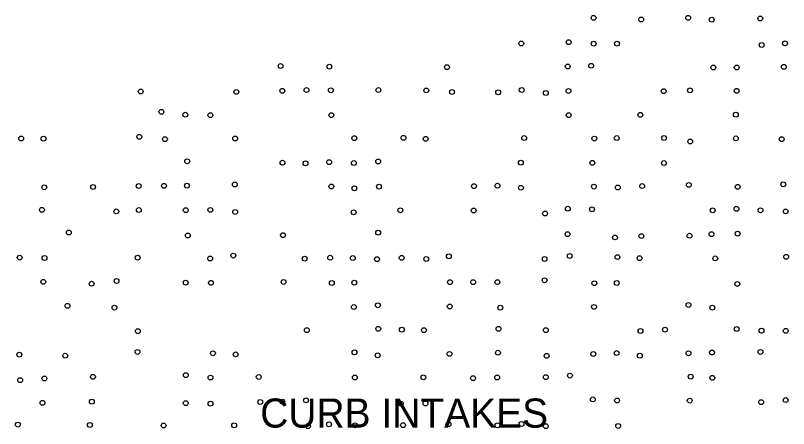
# Model space of a CAD drawing. Extents: x 20503438 to 20508873, y 7964251 to 7984667.
# Drawn here: x 20505042.3 to 20505360.8, y 7970624.5 to 7970794.8 of the extents above; entities that cross this region are included whole.
import ezdxf

# ---------------------------------------------------------------- set-up
doc = ezdxf.new("R2010")
doc.units = 0
doc.layers.add('SurSurveyPoints', color=7, linetype='Continuous')
doc.layers.add('SurTxtDrainage', color=7, linetype='Continuous')

msp = doc.modelspace()

# ---------------------------------------------------------------- linework, layer by layer
at = {"layer": 'SurSurveyPoints'}
for centre in [(20505280.47, 7970793.84), (20505300.05, 7970793.14), (20505319.42, 7970793.83), (20505329.14, 7970793.08), (20505349.12, 7970793.59), (20505250.68, 7970783.25), (20505270.21, 7970783.81), (20505280.51, 7970783.22), (20505290.11, 7970783.21), (20505349.71, 7970782.67), (20505359.33, 7970783.34), (20505151.54, 7970773.97), (20505171.66, 7970773.73), (20505220.06, 7970773.51), (20505269.82, 7970773.78), (20505279.49, 7970774.09), (20505329.8, 7970773.35), (20505339.43, 7970773.39), (20505358.81, 7970773.66), (20505093.94, 7970763.45), (20505133.3, 7970763.31), (20505152.26, 7970763.73), (20505162.21, 7970764.07), (20505172.27, 7970763.99), (20505191.83, 7970764.07), (20505211.54, 7970763.92), (20505222.14, 7970763.29), (20505250.88, 7970764.08), (20505270.13, 7970763.71), (20505309.33, 7970763.59), (20505320.2, 7970763.95), (20505339.39, 7970763.74), (20505241.17, 7970763.14), (20505260.81, 7970762.87), (20505102.46, 7970755.08), (20505112.33, 7970753.9), (20505122.64, 7970753.74), (20505172.47, 7970753.7), (20505270.21, 7970753.72), (20505299.71, 7970753.85), (20505339.07, 7970753.93), (20505093.36, 7970744.76), (20505181.94, 7970744.22), (20505202.2, 7970744.39), (20505251.87, 7970744.28), (20505290, 7970744.28), (20505309.51, 7970744.29), (20505339.09, 7970744.13), (20505044.71, 7970744.09), (20505053.91, 7970744.01), (20505103.9, 7970743.81), (20505132.86, 7970744.09), (20505211.3, 7970743.97), (20505280.77, 7970744.05), (20505320.28, 7970742.87), (20505357.93, 7970743.81), (20505113.04, 7970734.71), (20505191.75, 7970734.59), (20505152.33, 7970734.11), (20505161.78, 7970733.86), (20505171.56, 7970734.32), (20505181.71, 7970733.97), (20505250.51, 7970734.12), (20505279.94, 7970734.08), (20505309.44, 7970733.97), (20505132.68, 7970725.1), (20505358.6, 7970725.21), (20505054.2, 7970723.98), (20505074.31, 7970724.11), (20505093.08, 7970724.5), (20505103.51, 7970724.55), (20505112.96, 7970724.65), (20505172.47, 7970724.32), (20505181.96, 7970723.55), (20505192.11, 7970724.22), (20505231.2, 7970724.46), (20505240.89, 7970724.61), (20505250.54, 7970723.78), (20505280.6, 7970724.27), (20505290.44, 7970723.87), (20505300.47, 7970724.48), (20505319.69, 7970724.96), (20505339.82, 7970724.18), (20505053.24, 7970714.7), (20505083.88, 7970714.03), (20505093.17, 7970714.59), (20505112.48, 7970714.54), (20505122.62, 7970714.65), (20505132.86, 7970713.81), (20505181.64, 7970713.63), (20505200.88, 7970714.51), (20505231.06, 7970714.41), (20505260.49, 7970713.17), (20505269.85, 7970715.14), (20505279.82, 7970714.89), (20505329.52, 7970714.48), (20505339.35, 7970715.1), (20505349.23, 7970714.51), (20505359.57, 7970714.04), (20505064.35, 7970705.31), (20505113.35, 7970704.11), (20505152.52, 7970704.23), (20505191.73, 7970705.27), (20505269.77, 7970704.66), (20505289.29, 7970703.3), (20505300.16, 7970703.85), (20505320, 7970704), (20505329.01, 7970704.65), (20505339.78, 7970704.84), (20505044.09, 7970694.99), (20505054.3, 7970694.83), (20505092.69, 7970694.94), (20505122.56, 7970694.63), (20505132.07, 7970695.81), (20505161.48, 7970694.55), (20505171.96, 7970694.93), (20505181.29, 7970694.79), (20505191.25, 7970694.36), (20505201.44, 7970694.87), (20505211.54, 7970694.39), (20505220.86, 7970695.52), (20505260.29, 7970694.42), (20505270.61, 7970695.65), (20505290.29, 7970695.19), (20505299.42, 7970694.77), (20505330.59, 7970694.65), (20505359.77, 7970695.3), (20505053.8, 7970685), (20505073.72, 7970684.21), (20505083.99, 7970685.32), (20505112.43, 7970684.63), (20505122.89, 7970684.58), (20505152.79, 7970684.94), (20505172.63, 7970684.51), (20505181.9, 7970684.65), (20505221.31, 7970684.85), (20505230.88, 7970684.87), (20505240.86, 7970684.88), (20505260.29, 7970685.64), (20505280.76, 7970684.41), (20505290, 7970684.49), (20505339.68, 7970684.13), (20505063.76, 7970675.09), (20505083.14, 7970674.37), (20505181.7, 7970674.58), (20505191.58, 7970675.32), (20505221.22, 7970674.81), (20505242.02, 7970674.35), (20505280.64, 7970674.64), (20505319.59, 7970675.46), (20505329.39, 7970674.32), (20505092.74, 7970664.67), (20505162.33, 7970665.04), (20505191.77, 7970665.6), (20505201.5, 7970665.28), (20505210.58, 7970665.03), (20505241.28, 7970665.59), (20505260.8, 7970665.08), (20505299.8, 7970664.73), (20505309.87, 7970665.28), (20505339.42, 7970665.52), (20505349.64, 7970664.87), (20505359.62, 7970664.77), (20505043.93, 7970654.97), (20505092.58, 7970656.09), (20505123.68, 7970655.54), (20505133.06, 7970655.07), (20505181.99, 7970655.92), (20505221.1, 7970655.27), (20505241.06, 7970655.75), (20505280.38, 7970655.21), (20505289.96, 7970655.62), (20505319.59, 7970655.53), (20505329.26, 7970655.83), (20505349.2, 7970656.09), (20505062.85, 7970654.52), (20505191.55, 7970654.66), (20505261.16, 7970654.48), (20505299.49, 7970654.55), (20505074.24, 7970645.8), (20505112.49, 7970646.48), (20505122.7, 7970645.51), (20505142.54, 7970645.77), (20505182.14, 7970645.56), (20505210.32, 7970645.59), (20505240.73, 7970645.54), (20505260.82, 7970645.67), (20505270.73, 7970646.32), (20505320.47, 7970645.89), (20505044.3, 7970644.46), (20505054.26, 7970645.1), (20505230.83, 7970645.25), (20505329.39, 7970645.38), (20505162.01, 7970636.12), (20505280.18, 7970636.5), (20505290.15, 7970636.04), (20505320.08, 7970636.02), (20505359.6, 7970636.23), (20505053.47, 7970635.1), (20505073.79, 7970635.56), (20505112.48, 7970634.94), (20505122.67, 7970634.73), (20505143.17, 7970635.45), (20505152.24, 7970635.59), (20505201.08, 7970634.78), (20505211.23, 7970634.83), (20505349.47, 7970635.39), (20505220.73, 7970626.32), (20505250.77, 7970626.35), (20505043.34, 7970626.11), (20505072.99, 7970625.96), (20505103.36, 7970625.74), (20505132.42, 7970625.8), (20505162.81, 7970625.48), (20505171.47, 7970626.22), (20505182.18, 7970625.81), (20505201.99, 7970625.88), (20505240.91, 7970625.81), (20505260.76, 7970625.49), (20505290.57, 7970625.56)]:
    msp.add_circle(centre, 1, dxfattribs=at)

# ---------------------------------------------------------------- texts
at = {"layer": 'SurTxtDrainage'}
msp.add_text('CURB INTAKES', height=12, dxfattribs=at).set_placement((20505143.15, 7970624.87))

doc.saveas('drawing.dxf')
